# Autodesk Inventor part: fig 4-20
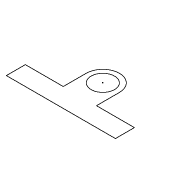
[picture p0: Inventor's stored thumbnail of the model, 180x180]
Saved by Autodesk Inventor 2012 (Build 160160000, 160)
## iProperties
Created: 2004-05
Part Number: fig 4-20
Document SubType Name: Modeling
Designer: CADCIM Technologies
Manufacturer: Standard
Standards Organization: Custom
Density: 1 g/cm^3
Material: Default
Author: CADCIM Technologies
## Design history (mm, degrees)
sketch "Sketch1"
  geometry: L1 (21.396, 25)-(21.396, 15.181); L2 (21.396, 15.181)-(77.829, 15.181); L3 (77.829, 15.181)-(77.829, 25); L4 (77.829, 25)-(58.204, 25); L5 (58.204, 25)-(58.204, 36.886); L6 (41.021, 36.886)-(41.021, 25); L7 (41.021, 25)-(21.396, 25); C1 r 6.072 at (49.612, 36.886); A1 r 8.592 centre (49.612, 36.886) between (58.204, 36.886) and (41.021, 36.886)
  constraints: 14 end point, 5 parallel, 2 centre point, 2 equal length, 2 point on circle, 2 tangent, 1 coincident, 1 perpendicular, 1 vertical, 1 other
